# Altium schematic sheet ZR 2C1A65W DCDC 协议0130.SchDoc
size A3
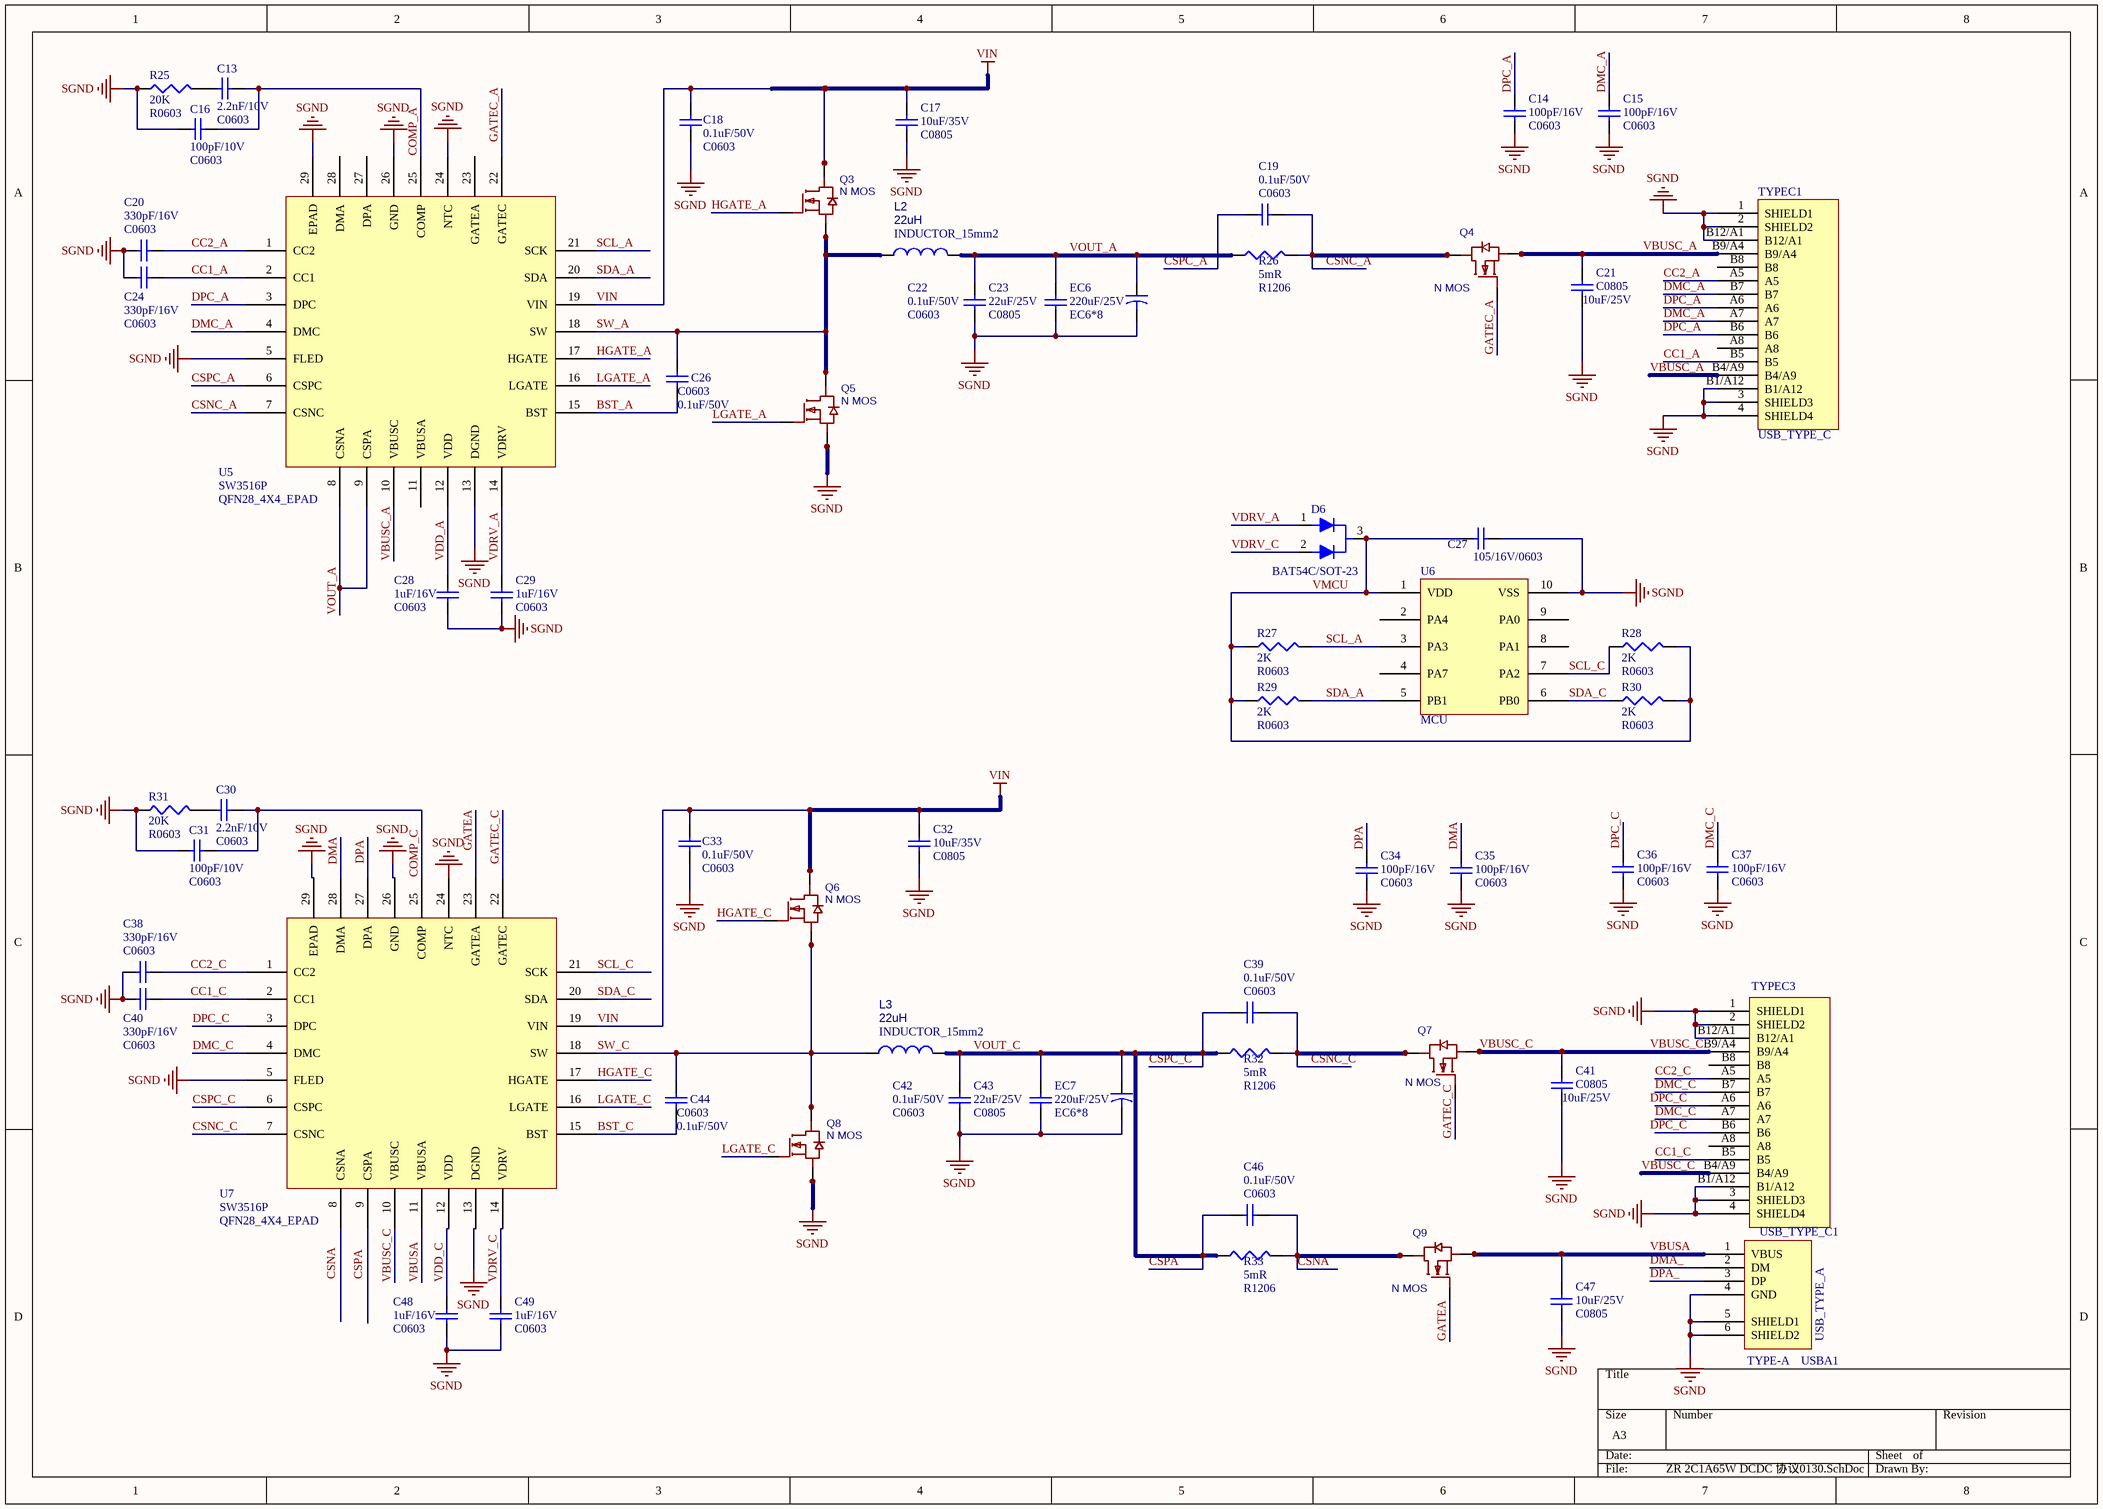
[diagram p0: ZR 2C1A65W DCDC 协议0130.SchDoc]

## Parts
C13  2.2nF/10V  [C0603]
C14  100pF/16V  [C0603]
C15  100pF/16V  [C0603]
C16  100pF/10V  [C0603]
C17  10uF/35V  [C0805]
C18  0.1uF/50V  [C0603]
C19  0.1uF/50V  [C0603]
C20  330pF/16V  [C0603]
C21  10uF/25V  [C0805]
C22  0.1uF/50V  [C0603]
C23  22uF/25V  [C0805]
C24  330pF/16V  [C0603]
C26  0.1uF/50V  [C0603]
C27  value 105/16V/0603  [0603C]  (hidden comment: Cap)
C28  1uF/16V  [C0603]
C29  1uF/16V  [C0603]
C30  2.2nF/10V  [C0603]
C31  100pF/10V  [C0603]
C32  10uF/35V  [C0805]
C33  0.1uF/50V  [C0603]
C34  100pF/16V  [C0603]
C35  100pF/16V  [C0603]
C36  100pF/16V  [C0603]
C37  100pF/16V  [C0603]
C38  330pF/16V  [C0603]
C39  0.1uF/50V  [C0603]
C40  330pF/16V  [C0603]
C41  10uF/25V  [C0805]
C42  0.1uF/50V  [C0603]
C43  22uF/25V  [C0805]
C44  0.1uF/50V  [C0603]
C46  0.1uF/50V  [C0603]
C47  10uF/25V  [C0805]
C48  1uF/16V  [C0603]
C49  1uF/16V  [C0603]
D6  BAT54C/SOT-23  [SOT-23]
EC6  220uF/25V  [EC6*8]
EC7  220uF/25V  [EC6*8]
L2  22uH  [INDUCTOR_15mm2]
L3  22uH  [INDUCTOR_15mm2]
Q3  N MOS  [SOT-23-3_L2.9-W1.3-P1.90-LS2.4-BR]
Q4  N MOS  [SOT-23-3_L2.9-W1.3-P1.90-LS2.4-BR]
Q5  N MOS  [SOT-23-3_L2.9-W1.3-P1.90-LS2.4-BR]
Q6  N MOS  [SOT-23-3_L2.9-W1.3-P1.90-LS2.4-BR]
Q7  N MOS  [SOT-23-3_L2.9-W1.3-P1.90-LS2.4-BR]
Q8  N MOS  [SOT-23-3_L2.9-W1.3-P1.90-LS2.4-BR]
Q9  N MOS  [SOT-23-3_L2.9-W1.3-P1.90-LS2.4-BR]
R25  20K  [R0603]
R26  5mR  [R1206]
R27  2K  [R0603]
R28  2K  [R0603]
R29  2K  [R0603]
R30  2K  [R0603]
R31  20K  [R0603]
R32  5mR  [R1206]
R33  5mR  [R1206]
TYPEC1  USB_TYPE_C  [USB_TYPE_C]
U5  SW3516P  [QFN28_4X4_EPAD]
U6  MCU  [MSOP10]
U7  SW3516P  [QFN28_4X4_EPAD]
USB_TYPE_C1  TYPEC3  [USB_TYPE_C]
USBA1  USB_TYPE_A  [TYPE-A]

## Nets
SGND: C14.1 C15.1 C16.2 C17.1 C18.1 C20.2 C21.1 C22.1 C23.1 C24.2 C27.2 C28.1 C29.1 C31.2 C32.1 C33.1 C34.1 C35.1 C36.1 C37.1 C38.2 C40.2 C41.1 C42.1 C43.1 C47.1 C48.1 C49.1 EC6.2 EC7.2 Q5.1(S) Q5.2(S) Q5.3(S) Q8.1(S) Q8.2(S) Q8.3(S) R25.1 R31.1 TYPEC1.1(SHIELD1) TYPEC1.2(SHIELD2) TYPEC1.3(SHIELD3) TYPEC1.4(SHIELD4) TYPEC1.B1/A12 TYPEC1.B12/A1 U5.5(FLED) U5.13(DGND) U5.24(NTC) U5.26(GND) U5.29(EPAD) U6.10(VSS) U7.5(FLED) U7.13(DGND) U7.24(NTC) U7.26(GND) U7.29(EPAD) USB_TYPE_C1.1(SHIELD1) USB_TYPE_C1.2(SHIELD2) USB_TYPE_C1.3(SHIELD3) USB_TYPE_C1.4(SHIELD4) USB_TYPE_C1.B1/A12 USB_TYPE_C1.B12/A1 USBA1.4(GND) USBA1.5(SHIELD1) USBA1.6(SHIELD2)
VIN: C17.2 C18.2 C32.2 C33.2 Q3.3(D) Q3.5(D) Q3.6(D) Q3.8(D) Q3.9(D) Q6.3(D) Q6.5(D) Q6.6(D) Q6.8(D) Q6.9(D) U5.19(VIN) U7.19(VIN)
BST_A: C26.1 U5.15(BST)
BST_C: C44.1 U7.15(BST)
CC1_A: C24.1 TYPEC1.B5 U5.2(CC1)
CC1_C: C40.1 U7.2(CC1) USB_TYPE_C1.B5
CC2_A: C20.1 TYPEC1.A5 U5.1(CC2)
CC2_C: C38.1 U7.1(CC2) USB_TYPE_C1.A5
COMP_A: C13.1 C16.1 U5.25(COMP)
COMP_C: C30.1 C31.1 U7.25(COMP)
CSNA: C46.1 Q9.3(D) Q9.5(D) Q9.6(D) Q9.8(D) Q9.9(D) R33.2
CSNC_A: C19.1 Q4.3(D) Q4.5(D) Q4.6(D) Q4.8(D) Q4.9(D) R26.2 U5.7(CSNC)
CSNC_C: C39.1 Q7.3(D) Q7.5(D) Q7.6(D) Q7.8(D) Q7.9(D) R32.2 U7.7(CSNC)
CSPA: C39.2 C42.2 C43.2 C46.2 EC7.1 L3.2 R32.1 R33.1 U7.6(CSPC)  [also labelled CSPC_C, VOUT_C]
CSPC_A: C19.2 U5.6(CSPC)
DMA: C35.2 U7.28(DMA)
DMA_: USBA1.2(DM)
DMC_A: C15.2 TYPEC1.A7 TYPEC1.B7 U5.4(DMC)
DMC_C: C37.2 U7.4(DMC) USB_TYPE_C1.A7 USB_TYPE_C1.B7
DPA: C34.2 U7.27(DPA)
DPA_: USBA1.3(DP)
DPC_A: C14.2 TYPEC1.A6 TYPEC1.B6 U5.3(DPC)
DPC_C: C36.2 U7.3(DPC)
GATEA: Q9.4(G) U7.23(GATEA)
GATEC_A: Q4.4(G) U5.22(GATEC)
GATEC_C: Q7.4(G) U7.22(GATEC)
HGATE_A: Q3.4(G) U5.17(HGATE)
HGATE_C: Q6.4(G) U7.17(HGATE)
LGATE_A: Q5.4(G) U5.16(LGATE)
LGATE_C: Q8.4(G) U7.16(LGATE)
SCL_A: R27.2 U5.21(SCK) U6.3(PA3)
SCL_C: R28.1 U6.7(PA2) U7.21(SCK)
SDA_A: R29.2 U5.20(SDA) U6.5(PB1)
SDA_C: R30.1 U6.6(PB0) U7.20(SDA)
SW_A: C26.2 L2.1 Q3.1(S) Q3.2(S) Q3.3(S) Q5.3(D) Q5.5(D) Q5.6(D) Q5.8(D) Q5.9(D) U5.18(SW)
SW_C: C44.2 L3.1 Q6.1(S) Q6.2(S) Q6.3(S) Q8.3(D) Q8.5(D) Q8.6(D) Q8.8(D) Q8.9(D) U7.18(SW)
VBUSA: C47.2 Q9.1(S) Q9.2(S) Q9.3(S) U7.11(VBUSA) USBA1.1(VBUS)
VBUSC_A: C21.2 Q4.1(S) Q4.2(S) Q4.3(S) TYPEC1.B4/A9 TYPEC1.B9/A4 U5.10(VBUSC)
VBUSC_C: C41.2 Q7.1(S) Q7.2(S) Q7.3(S) U7.10(VBUSC) USB_TYPE_C1.B4/A9 USB_TYPE_C1.B9/A4
VDD_A: C28.2 U5.12(VDD)
VDD_C: C48.2 U7.12(VDD)
VDRV_A: C29.2 D6.1 U5.14(VDRV)
VDRV_C: C49.2 D6.2 U7.14(VDRV)
VMCU: C27.1 D6.3 R27.1 R28.2 R29.1 R30.2 U6.1(VDD)
VOUT_A: C22.2 C23.2 EC6.1 L2.2 R26.1 U5.8(CSNA) U5.9(CSPA)
NetC13_2: C13.2 R25.2
NetC30_2: C30.2 R31.2

Not connected (* = marked no-connect by the designer): TYPEC1 A8 B8; U5 11(VBUSA) 23(GATEA) 27(DPA) 28(DMA); U6 2(PA4) 4(PA7) 8(PA1) 9(PA0); U7 8(CSNA) 9(CSPA); USB_TYPE_C1 A6 A8 B6 B8

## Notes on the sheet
- Labels drawn without touching a wire or pin: CSNA, CSPA, DPC_C

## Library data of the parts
C13 C16 C18-C20 C22-C24 C26 C28-C31 C33 C38-C40 C42-C44 C46 C48 C49 = CAP0603: Capacitor
C14 C15 C17 C21 C32 C34-C37 C41 C47 = CAP0805: Capacitor
C27 = Cap: Capacitor
D6 = D3
EC6 EC7 = Cap_Pol: Capacitor
L2 L3 = INDUCTOR
Q3-Q9 = AO3416_C479060: BOM_Manufacturer: PUOLOP; BOM_Manufacturer Part: AO3416; Contributor: LCSC
R25-R33 = RES: Resistor
U5 U7 = SW3517: IC
U6 = 153_MSOP10
USB_TYPE_C1 = USB_TYPE_C
USBA1 = TYPE-A-1: Value: TYPE-A1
